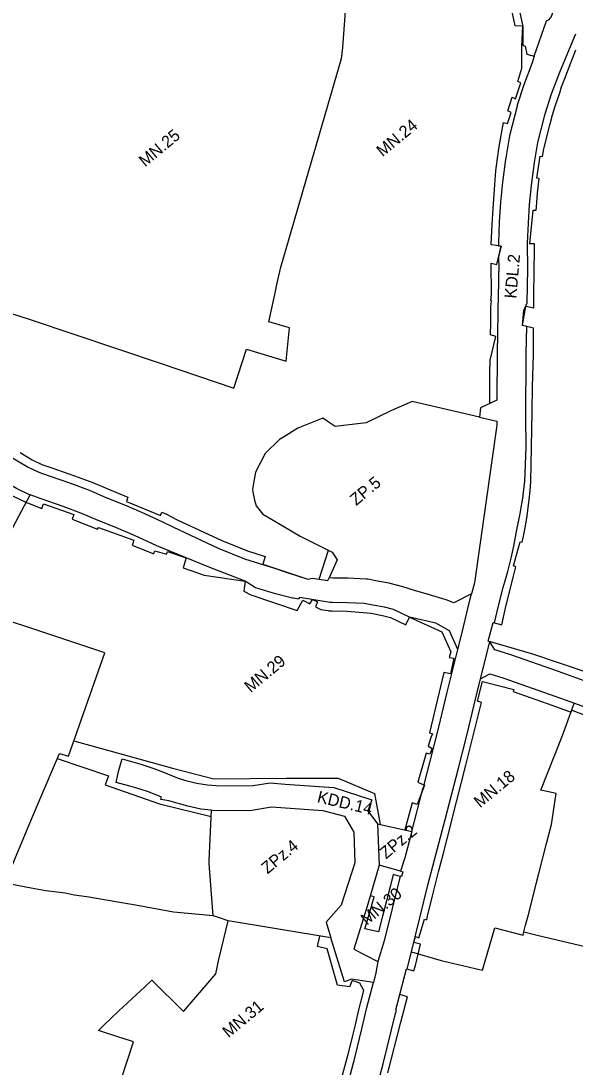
# Model space of a CAD drawing. Extents: x 7418616 to 7420822, y 5550745 to 5553106.
# Drawn here: x 7419907.9 to 7420139.9, y 5551619.2 to 5552057.3 of the extents above; entities that cross this region are included whole.
import ezdxf

# ---------------------------------------------------------------- set-up
doc = ezdxf.new("R2010")
doc.units = 0
for name, color, linetype in [('linie rozgraniczające', 7, 'Continuous'), ('nieprzekraczalne linie zabudowy', 7, 'Continuous'), ('przeznaczenia terenów', 7, 'Continuous')]:
    doc.layers.add(name, color=color, linetype=linetype)

msp = doc.modelspace()

# ---------------------------------------------------------------- linework, layer by layer
at = {"layer": 'linie rozgraniczające'}
for p, q in [((7420100.32, 5551781.7), (7420104.19, 5551797.21)), ((7420057.19, 5551721.04), (7420057.91, 5551703.72)), ((7420057.19, 5551721.04), (7420071.55, 5551717.83)), ((7420066.83, 5551701.23), (7420057.91, 5551703.72)), ((7420037.68, 5551673.26), (7419994.68, 5551680.44))]:
    msp.add_line(p, q, dxfattribs=at)
for points in [[(7420100.37, 5552106.25), (7420101.77, 5552103.96), (7420103.41, 5552100.49), (7420111.7, 5552078.16), (7420114.08, 5552070.97), (7420114.41, 5552069.91), (7420115.47, 5552066), (7420115.91, 5552064.54), (7420117.99, 5552054.98), (7420117.94, 5552047.13), (7420119.02, 5552046.72), (7420119.61, 5552043.3), (7420122.72, 5552042.44)], [(7420122.72, 5552042.44), (7420127.93, 5552057.32), (7420128.96, 5552057.88), (7420129.49, 5552058.46), (7420129.72, 5552058.64), (7420129.8, 5552058.79), (7420131.31, 5552062.66)], [(7419865.35, 5551916.02), (7419874.19, 5551912.4), (7419884.62, 5551907.67), (7419894.5, 5551903.44), (7419895.18, 5551904.22), (7419904.32, 5551934.63), (7419904.45, 5551934.6), (7419911.78, 5551932.3), (7419966.62, 5551913.81), (7419997.01, 5551903.55), (7420002.31, 5551919.81), (7420018.98, 5551914.74), (7420020.36, 5551928.71), (7420011.68, 5551931.3), (7420014.17, 5551942.65), (7420015.1, 5551946.85), (7420016.72, 5551954.2), (7420042.11, 5552041.51), (7420042.23, 5552042.46), (7420042.7, 5552046.08), (7420043.73, 5552061.39)], [(7420104.19, 5551797.21), (7420103.48, 5551797.52), (7420105.57, 5551805.35), (7420106.12, 5551805.21), (7420107.65, 5551811.83), (7420109.84, 5551820.04), (7420111.73, 5551826.65), (7420113.07, 5551832.33), (7420114.17, 5551837.29), (7420115.55, 5551844.17), (7420116.83, 5551851.02), (7420118.11, 5551858.28), (7420118.17, 5551858.65), (7420118.83, 5551864.55), (7420119.15, 5551871.55), (7420119.37, 5551878.95), (7420119.26, 5551891.1), (7420119.45, 5551917.81), (7420119.65, 5551929.34), (7420117.84, 5551929.68), (7420118.47, 5551935.98), (7420119.83, 5551939.19), (7420120.11, 5551953.41), (7420120.02, 5551964.19), (7420120.31, 5551972.59), (7420120.83, 5551980.43), (7420121.66, 5551988.39), (7420122.9, 5551998.03), (7420124.32, 5552006.35), (7420127.35, 5552018.36), (7420130.04, 5552026.67), (7420133.44, 5552035.85), (7420139.65, 5552050.57), (7420140.16, 5552051.86)], [(7420122.72, 5552042.44), (7420121.87, 5552039.73), (7420118.47, 5552030.55), (7420115.68, 5552021.92), (7420115.57, 5552021.54), (7420112.43, 5552009.11), (7420110.85, 5551999.96), (7420110.78, 5551999.2), (7420109.53, 5551989.72), (7420108.66, 5551981.34), (7420108.12, 5551973.11), (7420107.82, 5551964.25), (7420107.83, 5551963.12), (7420108.89, 5551962.93), (7420107.87, 5551958.51), (7420107.91, 5551953.57), (7420107.89, 5551952.29), (7420107.82, 5551952.31), (7420107.81, 5551944.87), (7420107.73, 5551944.78), (7420107.7, 5551943.38), (7420107.25, 5551917.99), (7420107.11, 5551898.55), (7420107.04, 5551898.52), (7420107.12, 5551898.43), (7420100.25, 5551895.28), (7420099.83, 5551891.37)], [(7420099.83, 5551891.37), (7420071.64, 5551897.93), (7420063.04, 5551894.09), (7420052.49, 5551889.02), (7420039.53, 5551887.42), (7420036.18, 5551889.69), (7420034.31, 5551890.96), (7420023.81, 5551886.78), (7420017.84, 5551882.97), (7420016.15, 5551881.97), (7420010.17, 5551876.15), (7420006.17, 5551868.33), (7420005.32, 5551863.7), (7420004.8, 5551860.84), (7420004.94, 5551860.06), (7420005.64, 5551856.61), (7420006.34, 5551854.21), (7420009.18, 5551850.76), (7420013.47, 5551848.24), (7420024.86, 5551841.53), (7420038.15, 5551834.87), (7420040.34, 5551831.64), (7420036.88, 5551823.99)], [(7420099.83, 5551891.37), (7420107.07, 5551889.68), (7420107.09, 5551887.93), (7420097.71, 5551821.9), (7420096.51, 5551817.38)], [(7419911.85, 5551858.76), (7419911.3, 5551858.97), (7419906.4, 5551861.31), (7419906.05, 5551861.5), (7419887.29, 5551872.61), (7419872.98, 5551881.75), (7419867.26, 5551885.53)], [(7419901.38, 5551876.12), (7419911, 5551870.42), (7419915.43, 5551868.31), (7419919.77, 5551866.82), (7419929.06, 5551863.57), (7419936.87, 5551860.6), (7419943.2, 5551857.88), (7419951.96, 5551854.38), (7419959.65, 5551851.03), (7419967.26, 5551847.57), (7419971.84, 5551845.24), (7419990.56, 5551836.44), (7420001.57, 5551832.03), (7420010.01, 5551829.32), (7420013.26, 5551828.36), (7420019.4, 5551826.32), (7420027.97, 5551823.48), (7420030.01, 5551823.94), (7420036.38, 5551822.88), (7420036.88, 5551823.99)], [(7419988.41, 5551682.49), (7419971.74, 5551683.99), (7419954.41, 5551687.23), (7419953.33, 5551687.39), (7419935.52, 5551690.42), (7419930.19, 5551691.21), (7419926.5, 5551692.07), (7419918.42, 5551693.04), (7419912.18, 5551694.12), (7419901.21, 5551696.19), (7419910.56, 5551718.7), (7419915.44, 5551730.19), (7419924.05, 5551750.44), (7419927.87, 5551749.43), (7419943.12, 5551792.61), (7419909.21, 5551803.94), (7419905.66, 5551805.01), (7419897.3, 5551807.68), (7419887.85, 5551810.69), (7419894.5, 5551825.83), (7419905.84, 5551847.52), (7419911.85, 5551858.76)], [(7420022.06, 5551815.48), (7420021.6, 5551815.57), (7420014.45, 5551817.36), (7420007.06, 5551819.55), (7420006.06, 5551819.87), (7420001.83, 5551822.68), (7419986.34, 5551828.67), (7419977.09, 5551832.39), (7419964.76, 5551837.39), (7419962.79, 5551838.39), (7419955.46, 5551841.73), (7419947.95, 5551845), (7419939.24, 5551848.48), (7419933, 5551851.16), (7419925.63, 5551853.96), (7419916.43, 5551857.18), (7419911.85, 5551858.76)], [(7420096.51, 5551817.38), (7420089.15, 5551813.59), (7420085.96, 5551814.83), (7420078.99, 5551816.99), (7420072.69, 5551818.82), (7420067.84, 5551820.26), (7420062.5, 5551821.67), (7420062.1, 5551821.76), (7420057.12, 5551822.65), (7420053.15, 5551823.45), (7420052.48, 5551823.54), (7420044.79, 5551823.85), (7420038.47, 5551823.95), (7420036.88, 5551823.99)], [(7420090.83, 5551794.05), (7420092.62, 5551801.23), (7420095, 5551811.27), (7420095.79, 5551814.67), (7420096.51, 5551817.38)], [(7420090.83, 5551794.05), (7420087.29, 5551801.92), (7420081.57, 5551805.01), (7420070.59, 5551807.52), (7420063.89, 5551810.75), (7420060.09, 5551811.75), (7420055.26, 5551812.62), (7420051.54, 5551813.37), (7420044.56, 5551813.65), (7420038.27, 5551813.75), (7420037.38, 5551813.78), (7420024.57, 5551815.78), (7420024.19, 5551815.42), (7420024.09, 5551815.17), (7420022.06, 5551815.48)], [(7420176.22, 5551769.04), (7420156.02, 5551776.41), (7420132.92, 5551784.81), (7420112.92, 5551791.86), (7420106.31, 5551793.86), (7420104.19, 5551797.21)], [(7420071.55, 5551717.83), (7420076.18, 5551735.64), (7420076.84, 5551737.4), (7420076.66, 5551737.47), (7420079.21, 5551747.32), (7420082.79, 5551761.46), (7420086.37, 5551776.18), (7420090.83, 5551794.05)], [(7420100.32, 5551781.7), (7420104.23, 5551783.83), (7420109.64, 5551782.2), (7420129.51, 5551775.2), (7420139.57, 5551771.54)], [(7420071.45, 5551667.47), (7420078.44, 5551695.92), (7420085.47, 5551722.83), (7420091.03, 5551744.31), (7420094.64, 5551758.53), (7420098.22, 5551773.29), (7420100.32, 5551781.7)], [(7420118.45, 5551675.77), (7420119.17, 5551678.56), (7420120.2, 5551682.57), (7420121.99, 5551689.6), (7420123.74, 5551696.43), (7420124.71, 5551700.23), (7420127.93, 5551712.79), (7420130.01, 5551720.81), (7420131.9, 5551733.7), (7420125.49, 5551735.21), (7420134.61, 5551758.02), (7420139.2, 5551770.67), (7420139.57, 5551771.54)], [(7420139.57, 5551771.54), (7420152.53, 5551766.83), (7420183.58, 5551755.49), (7420195.6, 5551751.2), (7420214.77, 5551744.27), (7420223, 5551741.05), (7420230.5, 5551738.58), (7420235.25, 5551737.38), (7420238.91, 5551736.05)], [(7419987.74, 5551726.79), (7419983.27, 5551727.23), (7419977.74, 5551728.41), (7419969.85, 5551730.72), (7419966.45, 5551731.3), (7419966.74, 5551732.2), (7419964.76, 5551733.05), (7419960.97, 5551734.57), (7419958.27, 5551735.42), (7419955.47, 5551736.23), (7419953.58, 5551736.84), (7419947.83, 5551738.36), (7419948.76, 5551742.99), (7419949.95, 5551746.91), (7419950.35, 5551748.23), (7419958.09, 5551746.09), (7419963.59, 5551744.27), (7419967.68, 5551742.71), (7419971.71, 5551741.05), (7419974.24, 5551739.97), (7419977.36, 5551739.06), (7419981.55, 5551738.04), (7419986.02, 5551737.34), (7419989.62, 5551737.07), (7419994.08, 5551737.02), (7420005.18, 5551737.07), (7420012.26, 5551738.18), (7420018.52, 5551737.72), (7420038.97, 5551736.23), (7420054.87, 5551731.07), (7420053.1, 5551726.44), (7420057.19, 5551721.04)], [(7420118.45, 5551675.77), (7420123.97, 5551674.44), (7420142.25, 5551670.08), (7420146.23, 5551669.09), (7420163.91, 5551664.7), (7420191.08, 5551657.95), (7420224.74, 5551654.62), (7420235.68, 5551651.83), (7420248.2, 5551648.89), (7420258.83, 5551645.64), (7420259.47, 5551645.41), (7420265.63, 5551643.27), (7420267.41, 5551648.29), (7420269.47, 5551654.1), (7420270.73, 5551657.71), (7420250.63, 5551664.82), (7420261.72, 5551696.13), (7420232.55, 5551705.25), (7420235.19, 5551721.06), (7420238.91, 5551736.05)], [(7419988.41, 5551682.49), (7419986.7, 5551704.44), (7419986.76, 5551705.68), (7419987.74, 5551726.79)], [(7419987.74, 5551726.79), (7420003.77, 5551726.68), (7420012.77, 5551728.15), (7420034.26, 5551726.66), (7420043.3, 5551724.2), (7420047.31, 5551717.62), (7420047.72, 5551704.75), (7420042.04, 5551686.94), (7420035.71, 5551679.8), (7420037.68, 5551673.26)], [(7420071.55, 5551717.83), (7420068.67, 5551706.8), (7420066.83, 5551701.23)], [(7420057.91, 5551703.72), (7420053.11, 5551687.42), (7420047.24, 5551668.58), (7420057.34, 5551663.36)], [(7420066.83, 5551701.23), (7420067.78, 5551700.97), (7420067.29, 5551698.98), (7420066.67, 5551699.14), (7420060, 5551671.99), (7420057.34, 5551663.36)], [(7419994.68, 5551680.44), (7419990.66, 5551681.87), (7419988.41, 5551682.49)], [(7419974.49, 5551594.78), (7419976.92, 5551602.43), (7419978.21, 5551606.48), (7419962.1, 5551610.56), (7419949.9, 5551613.99), (7419954.99, 5551629.76), (7419950.26, 5551631.32), (7419949.77, 5551631.48), (7419940.41, 5551634.57), (7419942.5, 5551636.57), (7419948.98, 5551642.71), (7419959.79, 5551652.81), (7419962.71, 5551655.57), (7419975.98, 5551642.42), (7419989.51, 5551658.28), (7419990.82, 5551664.22), (7419994.68, 5551680.44)], [(7420071.45, 5551667.47), (7420083.84, 5551663.85), (7420098.07, 5551660.51), (7420101.18, 5551659.78), (7420103.1, 5551666.48), (7420106.24, 5551677.45), (7420118.1, 5551674.39), (7420118.45, 5551675.77)], [(7420055.5, 5551654.67), (7420046.26, 5551655.96), (7420043.35, 5551654.92), (7420037.68, 5551673.26)], [(7420056.52, 5551608.96), (7420059.58, 5551620.5), (7420064.57, 5551641.06), (7420065.09, 5551643.07), (7420064.82, 5551643.14), (7420069.28, 5551660.28), (7420069.58, 5551660.29), (7420071.45, 5551667.47)], [(7420057.34, 5551663.36), (7420056.53, 5551658.63), (7420055.5, 5551654.67)], [(7420037.19, 5551583.05), (7420039.4, 5551591.99), (7420041.71, 5551600.73), (7420041.78, 5551601.13), (7420041.87, 5551601.52), (7420041.98, 5551601.9), (7420042.12, 5551602.25), (7420043.24, 5551606.48), (7420043.61, 5551607.69), (7420047.77, 5551623.56), (7420050.61, 5551635.2), (7420052.75, 5551644.09), (7420055.5, 5551654.67)]]:
    msp.add_lwpolyline(points, dxfattribs=at)
at = {"layer": 'nieprzekraczalne linie zabudowy'}
for points in [[(7420104.21, 5551897.1), (7420104.15, 5551910), (7420104.36, 5551915.24), (7420106.77, 5551925.1), (7420104.51, 5551925.79), (7420104.61, 5551930.66), (7420104.65, 5551937.37), (7420104.93, 5551940.23), (7420104.61, 5551940.26), (7420104.86, 5551942.78), (7420104.74, 5551955.85), (7420107.08, 5551955.25), (7420108.89, 5551962.93), (7420104.81, 5551963.54), (7420105.14, 5551972.13), (7420105.57, 5551978.54), (7420105.67, 5551980.64), (7420106.09, 5551986.68), (7420106.75, 5551994.43), (7420107.43, 5551999.69), (7420108.09, 5552004.61), (7420109.93, 5552014.68), (7420111.63, 5552014.29), (7420113.1, 5552018.92), (7420111.78, 5552019.62), (7420113.59, 5552025.4), (7420114.97, 5552024.68), (7420117.19, 5552031.35), (7420115.95, 5552031.89), (7420117.54, 5552037.43), (7420117.65, 5552046.79), (7420117.98, 5552055.01), (7420114.85, 5552055.26), (7420113, 5552063.79)], [(7420157.4, 5551780.17), (7420122.15, 5551792.15), (7420103.5, 5551797.51), (7420105.54, 5551805.35), (7420109.17, 5551804.41), (7420110.82, 5551812.02), (7420114.22, 5551825.36), (7420115.05, 5551828.67), (7420114.09, 5551829.08), (7420116.84, 5551839.08), (7420117.71, 5551838.97), (7420118.31, 5551841.57), (7420118.96, 5551845.03), (7420119.66, 5551849.07), (7420120.65, 5551856.67), (7420121.04, 5551860.61), (7420121.29, 5551864.21), (7420121.9, 5551893.53), (7420122.01, 5551904.12), (7420122.4, 5551917.38), (7420122.47, 5551928.66), (7420117.84, 5551929.68), (7420119.25, 5551937.84), (7420122.6, 5551937.09), (7420122.63, 5551943.14), (7420122.77, 5551951.71), (7420122.89, 5551962.17), (7420122.93, 5551963.85), (7420120.88, 5551963.94), (7420122.39, 5551978.04), (7420123.58, 5551977.95), (7420123.66, 5551979.31), (7420124.13, 5551985.27), (7420124.85, 5551991.23), (7420123.83, 5551991.47), (7420125.31, 5552000.62), (7420126.25, 5552000.5), (7420126.85, 5552003.66), (7420129.45, 5552014.2), (7420130.46, 5552017.98), (7420131.53, 5552021.61), (7420133.5, 5552027.18), (7420134.12, 5552029.72), (7420135.57, 5552033.1), (7420136.74, 5552036.02), (7420140.23, 5552045.22)], [(7419907.63, 5551876.48), (7419912.65, 5551873.51), (7419916.76, 5551871.55), (7419920.92, 5551870.12), (7419930.39, 5551866.81), (7419937.97, 5551863.93), (7419944.54, 5551861.12), (7419952.68, 5551857.81), (7419952.13, 5551856), (7419966.4, 5551850.18), (7419966.98, 5551851.52), (7419968.8, 5551850.71), (7419973.38, 5551848.38), (7419991.96, 5551839.65), (7420002.76, 5551835.33), (7420010.1, 5551832.96), (7420009.14, 5551829.72), (7420027.97, 5551823.48), (7420030.01, 5551823.94), (7420032.73, 5551823.49), (7420036.74, 5551835.58)], [(7419904.18, 5551858.56), (7419910.31, 5551855.59), (7419910.7, 5551855.45), (7419916.64, 5551853.07), (7419917.43, 5551855), (7419930.15, 5551850.56), (7419929.42, 5551848.69), (7419940.01, 5551844.4), (7419940.42, 5551845.13), (7419955.24, 5551839.81), (7419954.77, 5551838.5), (7419954.51, 5551837.72), (7419963.17, 5551834.27), (7419963.6, 5551834.2), (7419963.97, 5551835.4), (7419968.86, 5551833.94), (7419969.25, 5551835.08), (7419977.09, 5551832.39), (7419975.79, 5551828.23), (7419984.63, 5551825.23), (7420001.83, 5551822.68), (7420001.25, 5551818.42), (7420004.13, 5551816.96), (7420023.51, 5551810.38), (7420025.96, 5551814.68), (7420028.8, 5551813.23), (7420029.94, 5551814.95), (7420032.13, 5551813.95), (7420031.27, 5551811.97), (7420033.45, 5551810.86), (7420036.48, 5551810.39), (7420036.93, 5551810.3), (7420037.15, 5551810.28), (7420038.17, 5551810.25), (7420044.47, 5551810.15), (7420054.48, 5551809.21), (7420059.33, 5551808.34), (7420062.67, 5551807.45), (7420069.08, 5551804.37), (7420070.6, 5551807.52), (7420084.12, 5551801.48), (7420087.81, 5551793.08), (7420087.16, 5551790.63), (7420089.08, 5551790.42), (7420087.67, 5551783.84), (7420084.92, 5551784.45), (7420079, 5551759.21), (7420080.15, 5551758.72), (7420079.55, 5551757.15), (7420078.38, 5551753.5), (7420079.99, 5551752.61), (7420079.06, 5551750.24), (7420077.51, 5551750.61), (7420074.07, 5551738.46), (7420076.78, 5551737.25), (7420073.77, 5551729.16), (7420071.66, 5551729.9), (7420071.06, 5551727.75), (7420068.56, 5551718.5)], [(7420061.53, 5551616.82), (7420066.89, 5551638.06), (7420068.98, 5551645.92), (7420069.67, 5551648.63), (7420066.49, 5551649.56), (7420069.28, 5551660.28), (7420072.45, 5551659.49), (7420073.02, 5551661.71), (7420075.24, 5551670.59), (7420072.41, 5551671.36), (7420073.02, 5551673.83), (7420074.49, 5551673.36), (7420076.91, 5551681.17), (7420077.8, 5551680.84), (7420078.17, 5551682.33), (7420080.17, 5551690.95), (7420082.71, 5551700.95), (7420084.61, 5551708.16), (7420086.29, 5551714.8), (7420090.24, 5551730.19), (7420094.14, 5551745.64), (7420095.49, 5551751.2), (7420097.06, 5551757.34), (7420100.75, 5551771.92), (7420099.06, 5551772.37), (7420101.12, 5551780.64), (7420102.83, 5551780.16), (7420114.28, 5551777.23), (7420113.98, 5551776.43), (7420128.15, 5551771.43), (7420138.17, 5551767.79), (7420138.46, 5551768.6), (7420145.51, 5551766)], [(7419930.13, 5551755.82), (7419971.41, 5551744.36), (7419988.74, 5551739.93), (7420019.05, 5551740.21), (7420040.66, 5551740.23), (7420055.98, 5551733.78), (7420058.3, 5551720.79)], [(7419923.17, 5551748.38), (7419944.58, 5551741.13), (7419943.14, 5551737.32), (7419965.96, 5551729.36), (7419987.62, 5551724.12)], [(7420066.62, 5551698.96), (7420063.78, 5551699.78), (7420062.57, 5551695.22), (7420059.3, 5551682.36), (7420057.58, 5551675.78), (7420051.9, 5551677.08), (7420052.82, 5551680.34), (7420055.76, 5551690.43), (7420054.13, 5551690.89)], [(7420041.85, 5551613.31), (7420045.25, 5551625.61), (7420046.72, 5551631.86), (7420047.96, 5551636.82), (7420049.27, 5551642.58), (7420051.51, 5551651.24), (7420049.76, 5551654.31), (7420046.52, 5551655.4), (7420045.48, 5551652.78), (7420040.49, 5551653.51), (7420036.14, 5551668.71), (7420032.01, 5551669.71), (7420033.02, 5551674.04)]]:
    msp.add_lwpolyline(points, dxfattribs=at)

# ---------------------------------------------------------------- texts
at = {"layer": 'przeznaczenia terenów'}
for s, rotation, p in [('MN.24', 39.8439, (7420059.32, 5552000.1)), ('MN.25', 39.8439, (7419959.9, 5551995.9)), ('KDL.2', 85.0437, (7420115.26, 5551940.88)), ('ZP.5', 39.8439, (7420048.25, 5551854.05)), ('MN.29', 39.8439, (7420004.06, 5551775.75)), ('MN.18', 39.8439, (7420100.11, 5551727.51)), ('KDD.14', 346.7638, (7420031.63, 5551730.15)), ('ZPz.2', 39.8439, (7420060.74, 5551706.09)), ('ZPz.4', 39.8439, (7420011.14, 5551699.82)), ('MN.30', 39.8439, (7420052.76, 5551678.36)), ('MN.31', 39.8439, (7419994.85, 5551631.19))]:
    msp.add_text(s, height=5, rotation=rotation, dxfattribs=at).set_placement(p)

doc.saveas('drawing.dxf')
